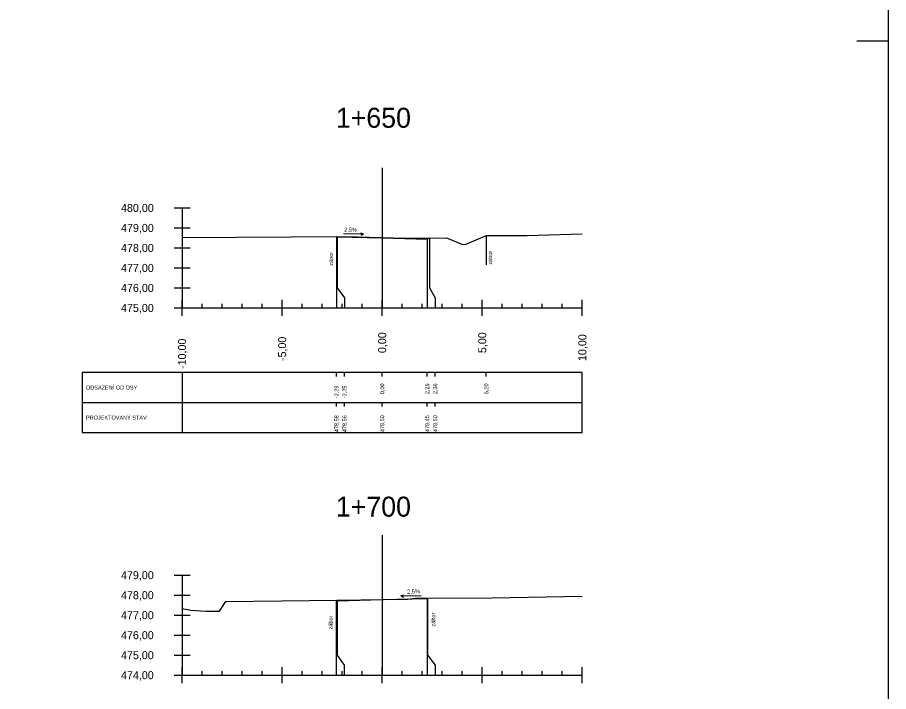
# Model space of a CAD drawing. Extents: x -631407 to -631215, y -1089700 to -1088598.
# Drawn here: x -631258.91 to -631215.38, y -1089059.73 to -1089026.02 of the extents above; entities that cross this region are included whole.
import ezdxf

# ---------------------------------------------------------------- set-up
doc = ezdxf.new("R2010")
doc.units = 0
for name, color, linetype in [('08_LEGENDA_HV', 7, 'Continuous'), ('59', 7, 'Continuous'), ('DTM-Breaklines', 7, 'Continuous'), ('NIVELETA_VYSKY', 7, 'Continuous'), ('REZ_BODY', 7, 'Continuous'), ('REZ_ODSTUPY', 7, 'Continuous'), ('REZ_POPIS', 7, 'Continuous'), ('REZ_RAMY', 7, 'Continuous'), ('REZ_STANICENI', 7, 'Continuous'), ('REZ_SVISLE', 7, 'Continuous'), ('REZ_TENKA', 7, 'Continuous'), ('REZ_TLUSTA', 7, 'Continuous'), ('TABULKA_POPIS', 7, 'Continuous'), ('TEREN', 7, 'Continuous'), ('zábor', 7, 'Continuous')]:
    doc.layers.add(name, color=color, linetype=linetype)

msp = doc.modelspace()

# ---------------------------------------------------------------- linework, layer by layer
at = {"layer": '08_LEGENDA_HV'}
msp.add_lwpolyline([(-631215.384, -1089086.599), (-631215.384, -1088967.799), (-631407.014, -1088967.799), (-631407.014, -1089086.599)], close=True, dxfattribs=at)
at = {"layer": '59'}
for p, q in [((-631251.088, -1089035.546), (-631250.288, -1089035.546)), ((-631250.688, -1089035.546), (-631250.688, -1089040.546)), ((-631251.088, -1089036.546), (-631250.288, -1089036.546)), ((-631251.088, -1089037.546), (-631250.288, -1089037.546)), ((-631251.088, -1089038.546), (-631250.288, -1089038.546)), ((-631251.088, -1089039.546), (-631250.288, -1089039.546)), ((-631251.088, -1089040.546), (-631250.288, -1089040.546)), ((-631251.088, -1089053.907), (-631250.288, -1089053.907)), ((-631250.688, -1089053.907), (-631250.688, -1089058.907)), ((-631251.088, -1089054.907), (-631250.288, -1089054.907)), ((-631251.088, -1089055.907), (-631250.288, -1089055.907)), ((-631251.088, -1089056.907), (-631250.288, -1089056.907)), ((-631251.088, -1089057.907), (-631250.288, -1089057.907)), ((-631251.088, -1089058.907), (-631250.288, -1089058.907))]:
    msp.add_line(p, q, dxfattribs=at)
at = {"layer": 'DTM-Breaklines'}
msp.add_line((-631216.965, -1089027.199), (-631215.384, -1089027.199), dxfattribs=at)
at = {"layer": 'REZ_RAMY'}
for p, q in [((-631255.688, -1089043.779), (-631255.688, -1089046.779)), ((-631250.688, -1089043.779), (-631250.688, -1089046.779)), ((-631242.973, -1089043.979), (-631242.973, -1089043.779)), ((-631242.573, -1089043.979), (-631242.573, -1089043.779)), ((-631240.688, -1089043.979), (-631240.688, -1089043.779)), ((-631238.438, -1089043.979), (-631238.438, -1089043.779)), ((-631238.038, -1089043.979), (-631238.038, -1089043.779)), ((-631235.486, -1089043.979), (-631235.486, -1089043.779)), ((-631255.688, -1089045.279), (-631230.688, -1089045.279)), ((-631242.973, -1089045.479), (-631242.973, -1089045.279)), ((-631242.573, -1089045.479), (-631242.573, -1089045.279)), ((-631240.688, -1089045.479), (-631240.688, -1089045.279)), ((-631238.438, -1089045.479), (-631238.438, -1089045.279)), ((-631238.038, -1089045.479), (-631238.038, -1089045.279))]:
    msp.add_line(p, q, dxfattribs=at)
msp.add_lwpolyline([(-631255.688, -1089043.779), (-631255.688, -1089046.779), (-631230.688, -1089046.779), (-631230.688, -1089043.779)], close=True, dxfattribs=at)
at = {"layer": 'REZ_SVISLE'}
for points in [[(-631242.973, -1089036.97), (-631242.973, -1089039.546), (-631242.973, -1089040.046), (-631242.973, -1089040.546)], [(-631242.938, -1089036.988), (-631242.938, -1089039.546), (-631242.573, -1089040.046), (-631242.573, -1089040.546)], [(-631240.688, -1089037.044), (-631240.688, -1089039.546), (-631240.688, -1089040.046), (-631240.688, -1089040.546)], [(-631238.438, -1089037.1), (-631238.438, -1089039.546), (-631238.438, -1089040.046), (-631238.438, -1089040.546)], [(-631238.326, -1089037.044), (-631238.326, -1089039.546), (-631238.038, -1089040.046), (-631238.038, -1089040.546)], [(-631242.992, -1089055.156), (-631242.992, -1089057.907), (-631242.992, -1089058.407), (-631242.992, -1089058.907)], [(-631242.938, -1089055.183), (-631242.938, -1089057.907), (-631242.592, -1089058.407), (-631242.592, -1089058.907)], [(-631240.688, -1089055.126), (-631240.688, -1089057.907), (-631240.688, -1089058.407), (-631240.688, -1089058.907)], [(-631238.438, -1089055.07), (-631238.438, -1089057.907), (-631238.438, -1089058.407), (-631238.438, -1089058.907)], [(-631238.419, -1089055.059), (-631238.419, -1089057.907), (-631238.038, -1089058.407), (-631238.038, -1089058.907)]]:
    msp.add_lwpolyline(points, dxfattribs=at)
at = {"layer": 'REZ_TENKA'}
for p, q in [((-631249.688, -1089040.546), (-631249.688, -1089040.346)), ((-631248.688, -1089040.546), (-631248.688, -1089040.346)), ((-631247.688, -1089040.546), (-631247.688, -1089040.346)), ((-631246.688, -1089040.546), (-631246.688, -1089040.346)), ((-631244.688, -1089040.546), (-631244.688, -1089040.346)), ((-631243.688, -1089040.546), (-631243.688, -1089040.346)), ((-631242.688, -1089040.546), (-631242.688, -1089040.346)), ((-631241.688, -1089040.546), (-631241.688, -1089040.346)), ((-631239.688, -1089040.546), (-631239.688, -1089040.346)), ((-631238.688, -1089040.546), (-631238.688, -1089040.346)), ((-631237.688, -1089040.546), (-631237.688, -1089040.346)), ((-631236.688, -1089040.546), (-631236.688, -1089040.346)), ((-631234.688, -1089040.546), (-631234.688, -1089040.346)), ((-631233.688, -1089040.546), (-631233.688, -1089040.346)), ((-631232.688, -1089040.546), (-631232.688, -1089040.346)), ((-631231.688, -1089040.546), (-631231.688, -1089040.346)), ((-631249.688, -1089058.907), (-631249.688, -1089058.707)), ((-631248.688, -1089058.907), (-631248.688, -1089058.707)), ((-631247.688, -1089058.907), (-631247.688, -1089058.707)), ((-631246.688, -1089058.907), (-631246.688, -1089058.707)), ((-631244.688, -1089058.907), (-631244.688, -1089058.707)), ((-631243.688, -1089058.907), (-631243.688, -1089058.707)), ((-631242.688, -1089058.907), (-631242.688, -1089058.707)), ((-631241.688, -1089058.907), (-631241.688, -1089058.707)), ((-631239.688, -1089058.907), (-631239.688, -1089058.707)), ((-631238.688, -1089058.907), (-631238.688, -1089058.707)), ((-631237.688, -1089058.907), (-631237.688, -1089058.707)), ((-631236.688, -1089058.907), (-631236.688, -1089058.707)), ((-631234.688, -1089058.907), (-631234.688, -1089058.707)), ((-631233.688, -1089058.907), (-631233.688, -1089058.707)), ((-631232.688, -1089058.907), (-631232.688, -1089058.707)), ((-631231.688, -1089058.907), (-631231.688, -1089058.707))]:
    msp.add_line(p, q, dxfattribs=at)
at = {"layer": 'REZ_TLUSTA'}
for p, q in [((-631240.688, -1089033.546), (-631240.688, -1089040.546)), ((-631250.688, -1089040.946), (-631250.688, -1089040.146)), ((-631245.688, -1089040.946), (-631245.688, -1089040.146)), ((-631240.688, -1089040.946), (-631240.688, -1089040.146)), ((-631235.688, -1089040.946), (-631235.688, -1089040.146)), ((-631230.688, -1089040.946), (-631230.688, -1089040.146)), ((-631250.688, -1089040.546), (-631230.688, -1089040.546)), ((-631240.688, -1089051.907), (-631240.688, -1089058.907)), ((-631250.688, -1089059.307), (-631250.688, -1089058.507)), ((-631245.688, -1089059.307), (-631245.688, -1089058.507)), ((-631240.688, -1089059.307), (-631240.688, -1089058.507)), ((-631235.688, -1089059.307), (-631235.688, -1089058.507)), ((-631230.688, -1089059.307), (-631230.688, -1089058.507)), ((-631250.688, -1089058.907), (-631230.688, -1089058.907))]:
    msp.add_line(p, q, dxfattribs=at)
at = {"layer": 'TEREN'}
for points in [[(-631250.688, -1089037.02), (-631242.526, -1089036.967), (-631239.545, -1089037.055), (-631239.007, -1089037.053), (-631237.472, -1089037.033), (-631236.7, -1089037.352), (-631236.536, -1089037.378), (-631235.554, -1089036.957), (-631235.486, -1089036.917), (-631233.438, -1089036.92), (-631230.688, -1089036.848)], [(-631242.973, -1089036.97), (-631242.938, -1089036.988), (-631240.688, -1089037.044), (-631238.438, -1089037.1), (-631238.326, -1089037.044)], [(-631250.688, -1089055.568), (-631250.252, -1089055.654), (-631249.506, -1089055.708), (-631248.921, -1089055.707), (-631248.828, -1089055.704), (-631248.819, -1089055.698), (-631248.496, -1089055.218), (-631242.937, -1089055.155), (-631239.403, -1089055.102), (-631239.036, -1089055.063), (-631235.196, -1089055.037), (-631230.688, -1089054.95)], [(-631242.992, -1089055.156), (-631242.938, -1089055.183), (-631240.688, -1089055.126), (-631238.438, -1089055.07), (-631238.419, -1089055.059)]]:
    msp.add_lwpolyline(points, dxfattribs=at)
at = {"layer": 'zábor'}
for p, q in [((-631241.621, -1089036.865), (-631242.629, -1089036.839)), ((-631241.621, -1089036.865), (-631241.76, -1089036.922)), ((-631241.621, -1089036.865), (-631241.757, -1089036.8)), ((-631235.486, -1089036.917), (-631235.486, -1089038.398)), ((-631239.755, -1089054.947), (-631239.618, -1089054.882)), ((-631239.755, -1089054.947), (-631238.746, -1089054.922)), ((-631239.755, -1089054.947), (-631239.615, -1089055.005))]:
    msp.add_line(p, q, dxfattribs=at)

# ---------------------------------------------------------------- texts
at = {"layer": 'NIVELETA_VYSKY'}
for s, p in [('478,58', (-631242.873, -1089046.755)), ('478,56', (-631242.473, -1089046.755)), ('478,50', (-631240.588, -1089046.755)), ('478,45', (-631238.338, -1089046.755)), ('478,50', (-631237.938, -1089046.755))]:
    msp.add_text(s, height=0.2, rotation=90, dxfattribs=at).set_placement(p)
at = {"layer": 'REZ_BODY'}
for s, p in [('0,00', (-631240.588, -1089044.858)), ('2,25', (-631238.338, -1089044.858)), ('2,36', (-631237.938, -1089044.858)), ('5,20', (-631235.386, -1089044.858)), ('-2,29', (-631242.873, -1089045.057)), ('-2,25', (-631242.473, -1089045.057))]:
    msp.add_text(s, height=0.2, rotation=90, dxfattribs=at).set_placement(p)
at = {"layer": 'REZ_ODSTUPY'}
for s, p in [('0,00', (-631240.488, -1089042.804)), ('5,00', (-631235.488, -1089042.804)), ('-10,00', (-631250.488, -1089043.597)), ('-5,00', (-631245.488, -1089043.201)), ('10,00', (-631230.488, -1089043.201))]:
    msp.add_text(s, height=0.4, rotation=90, dxfattribs=at).set_placement(p)
at = {"layer": 'REZ_POPIS'}
for s, p in [('480,00', (-631253.739, -1089035.746)), ('479,00', (-631253.739, -1089036.746)), ('478,00', (-631253.739, -1089037.746)), ('477,00', (-631253.739, -1089038.746)), ('476,00', (-631253.739, -1089039.746)), ('475,00', (-631253.739, -1089040.746)), ('479,00', (-631253.739, -1089054.107)), ('478,00', (-631253.739, -1089055.107)), ('477,00', (-631253.739, -1089056.107)), ('476,00', (-631253.739, -1089057.107)), ('475,00', (-631253.739, -1089058.107)), ('474,00', (-631253.739, -1089059.107))]:
    msp.add_text(s, height=0.4, dxfattribs=at).set_placement(p)
at = {"layer": 'REZ_STANICENI'}
for s, p in [('1+650', (-631243.006, -1089031.538)), ('1+700', (-631243.006, -1089050.981))]:
    msp.add_text(s, height=1, dxfattribs=at).set_placement(p)
at = {"layer": 'TABULKA_POPIS'}
for s, p in [('ODSAZENÍ OD OSY', (-631255.488, -1089044.629)), ('PROJEKTOVANÝ STAV', (-631255.488, -1089046.129))]:
    msp.add_text(s, height=0.2, dxfattribs=at).set_placement(p)
at = {"layer": 'zábor'}
for s, rotation, p in [('2,5%', 358.5679, (-631242.584, -1089036.727)), ('zábor', 90, (-631243.143, -1089038.434)), ('zábor', 90, (-631235.194, -1089038.381)), ('2,5%', 1.4321, (-631239.438, -1089054.826)), ('zábor', 90, (-631243.162, -1089056.619)), ('zábor', 90, (-631238.036, -1089056.473))]:
    msp.add_text(s, height=0.2, rotation=rotation, dxfattribs=at).set_placement(p)

doc.saveas('drawing.dxf')
